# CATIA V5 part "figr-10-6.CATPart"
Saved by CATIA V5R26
Part number: Part1
Bounding box of the stored display mesh (mm): x -9.888 to 10, y -9.972 to 9.972, z 0 to 10
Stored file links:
  D:\_Deepak\CATIA\CATIA V5-6R2016_Deepak\Resources\Part files\Partfiles\c10_catia_v5_6r2016_prt\figr-10-6.CATPart
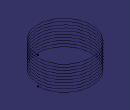
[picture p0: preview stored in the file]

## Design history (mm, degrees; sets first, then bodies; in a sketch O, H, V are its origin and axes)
Set1
  Helix1: Direction {line stored without definition}, RefPoint {point type Coord, X 10, Y 0, Z 0}, Pitch 1, Height 10, TaperAngle 0
Body1 (main body)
